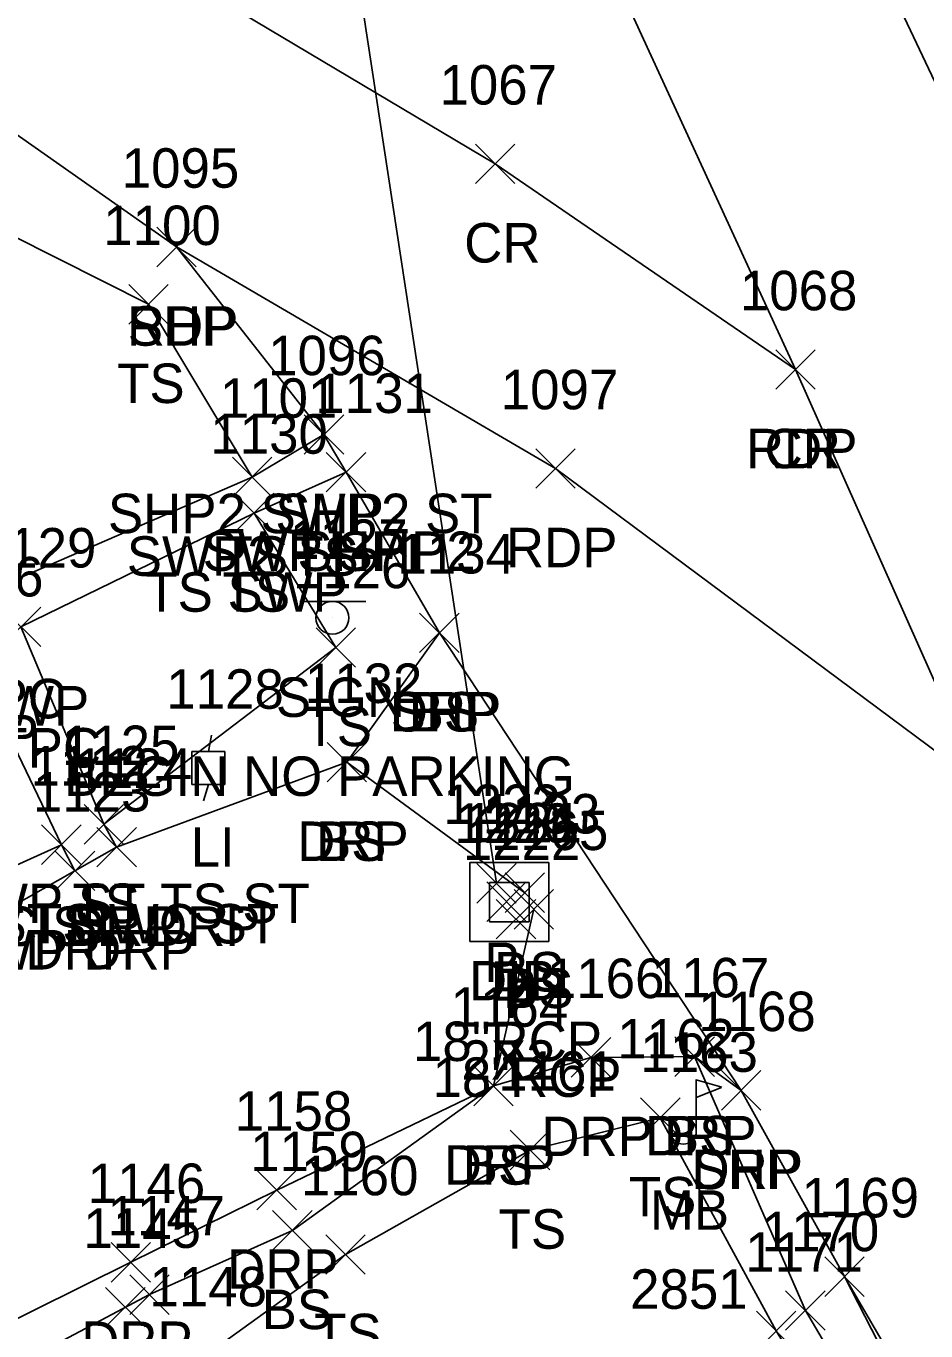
# Model space of a CAD drawing. Extents: x 1504228 to 1506103, y 437717 to 440106.
# Drawn here: x 1505081.8 to 1505127.3, y 438311.9 to 438378 of the extents above; entities that cross this region are included whole.
import ezdxf

# ---------------------------------------------------------------- set-up
doc = ezdxf.new("R2010")
doc.units = 0
for name, color, linetype in [('D_A', 7, 'Continuous'), ('D_C', 7, 'Continuous'), ('D_I', 7, 'Continuous'), ('D_TIC', 7, 'Continuous'), ('DCP', 7, 'Continuous'), ('DD', 7, 'Continuous'), ('DS', 7, 'Continuous'), ('L_A', 7, 'Continuous'), ('L_C', 7, 'Continuous'), ('L_I', 7, 'Continuous'), ('L_TIC', 7, 'Continuous'), ('LBF', 7, 'Continuous'), ('LELB', 7, 'Continuous'), ('LMB', 7, 'Continuous'), ('P_A', 7, 'Continuous'), ('P_I', 7, 'Continuous'), ('P_TIC', 7, 'Continuous'), ('PET', 7, 'Continuous'), ('PRC', 7, 'Continuous'), ('PSP', 7, 'Continuous'), ('R_A', 7, 'Continuous'), ('R_I', 7, 'Continuous'), ('R_TIC', 7, 'Continuous'), ('RDP', 7, 'Continuous'), ('RSW', 7, 'Continuous'), ('S_A', 7, 'Continuous'), ('S_C', 7, 'Continuous'), ('S_I', 7, 'Continuous'), ('SSGN', 7, 'Continuous'), ('U_A', 7, 'Continuous'), ('U_I', 7, 'Continuous'), ('ULP', 7, 'Continuous')]:
    doc.layers.add(name, color=color, linetype=linetype)

msp = doc.modelspace()

# ---------------------------------------------------------------- linework, layer by layer
at = {"layer": 'D_TIC'}
for points in [[(1505104.611, 438333.574), (1505106.611, 438335.574)], [(1505106.611, 438333.574), (1505104.611, 438335.574)], [(1505105.113, 438332.645), (1505107.113, 438334.645)], [(1505107.113, 438332.645), (1505105.113, 438334.645)], [(1505105.599, 438331.757), (1505107.599, 438333.757)], [(1505107.599, 438331.757), (1505105.599, 438333.757)], [(1505122.23, 438313.656), (1505124.23, 438315.656)], [(1505124.23, 438313.656), (1505122.23, 438315.656)], [(1505120.248, 438311.943), (1505122.248, 438313.943)], [(1505122.248, 438311.943), (1505120.248, 438313.943)]]:
    msp.add_lwpolyline(points, dxfattribs=at)
at = {"layer": 'DCP'}
msp.add_lwpolyline([(1505105.611, 438334.574), (1505096.144, 438396.524)], dxfattribs=at)
at = {"layer": 'DD'}
for points in [[(1505123.23, 438314.656), (1505130.775, 438299.935), (1505150.445, 438267.376), (1505153.96, 438259.428), (1505154.819, 438247.207), (1505159.704, 438235.931), (1505164.132, 438229.451)], [(1505121.248, 438312.943), (1505129.281, 438299.278), (1505148.937, 438266.102), (1505152.605, 438259.415), (1505152.899, 438247.284), (1505158.089, 438235.239), (1505161.473, 438228.418)]]:
    msp.add_lwpolyline(points, dxfattribs=at)
at = {"layer": 'DS'}
for p, q in [((1505104.255, 438335.622), (1505108.255, 438335.622)), ((1505104.255, 438331.622), (1505104.255, 438335.622)), ((1505108.255, 438335.622), (1505108.255, 438331.622)), ((1505105.255, 438332.622), (1505105.255, 438334.622)), ((1505105.255, 438334.622), (1505107.255, 438334.622)), ((1505107.255, 438334.622), (1505107.255, 438332.622)), ((1505106.26, 438333.623), (1505106.26, 438333.623)), ((1505106.26, 438333.623), (1505106.26, 438333.623)), ((1505107.255, 438332.622), (1505105.255, 438332.622)), ((1505108.255, 438331.622), (1505104.255, 438331.622))]:
    msp.add_line(p, q, dxfattribs=at)
at = {"layer": 'L_TIC'}
for points in [[(1505086.996, 438362.895), (1505088.996, 438364.895)], [(1505088.996, 438362.895), (1505086.996, 438364.895)], [(1505092.24, 438354.147), (1505094.24, 438356.147)], [(1505094.24, 438354.147), (1505092.24, 438356.147)], [(1505092.336, 438352.326), (1505094.336, 438354.326)], [(1505094.336, 438352.326), (1505092.336, 438354.326)], [(1505101.72, 438346.262), (1505103.72, 438348.262)], [(1505103.72, 438346.262), (1505101.72, 438348.262)], [(1505096.48, 438345.519), (1505098.48, 438347.519)], [(1505098.48, 438345.519), (1505096.48, 438347.519)], [(1505097.031, 438339.705), (1505099.031, 438341.705)], [(1505099.031, 438339.705), (1505097.031, 438341.705)], [(1505084.734, 438336.561), (1505086.734, 438338.561)], [(1505086.734, 438336.561), (1505084.734, 438338.561)], [(1505084.734, 438336.561), (1505086.734, 438338.561)], [(1505086.734, 438336.561), (1505084.734, 438338.561)], [(1505082.583, 438335.527), (1505084.583, 438337.527)], [(1505084.583, 438335.527), (1505082.583, 438337.527)], [(1505085.379, 438335.405), (1505087.379, 438337.405)], [(1505087.379, 438335.405), (1505085.379, 438337.405)], [(1505106.042, 438333.097), (1505108.042, 438335.097)], [(1505108.042, 438333.097), (1505106.042, 438335.097)], [(1505106.496, 438332.257), (1505108.496, 438334.257)], [(1505108.496, 438332.257), (1505106.496, 438334.257)], [(1505114.64, 438324.797), (1505116.64, 438326.797)], [(1505116.64, 438324.797), (1505114.64, 438326.797)], [(1505104.46, 438323.312), (1505106.46, 438325.312)], [(1505106.46, 438323.312), (1505104.46, 438325.312)], [(1505112.899, 438321.703), (1505114.899, 438323.703)], [(1505114.899, 438321.703), (1505112.899, 438323.703)], [(1505106.308, 438320.068), (1505108.308, 438322.068)], [(1505108.308, 438320.068), (1505106.308, 438322.068)], [(1505094.277, 438315.997), (1505096.277, 438317.997)], [(1505096.277, 438315.997), (1505094.277, 438317.997)], [(1505096.967, 438314.777), (1505098.967, 438316.777)], [(1505098.967, 438314.777), (1505096.967, 438316.777)], [(1505087.045, 438312.744), (1505089.045, 438314.744)], [(1505089.045, 438312.744), (1505087.045, 438314.744)], [(1505085.823, 438312.111), (1505087.823, 438314.111)], [(1505087.823, 438312.111), (1505085.823, 438314.111)], [(1505120.248, 438311.943), (1505122.248, 438313.943)], [(1505122.248, 438311.943), (1505120.248, 438313.943)], [(1505118.766, 438310.905), (1505120.766, 438312.905)], [(1505120.766, 438310.905), (1505118.766, 438312.905)]]:
    msp.add_lwpolyline(points, dxfattribs=at)
at = {"layer": 'LBF'}
msp.add_lwpolyline([(1505086.379, 438336.405), (1505085.734, 438337.561)], dxfattribs=at)
at = {"layer": 'LELB'}
for points in [[(1505059.009, 438383.324), (1505071.79, 438372.048), (1505087.996, 438363.895), (1505093.24, 438355.147)], [(1505085.734, 438337.561), (1505097.48, 438346.519), (1505093.336, 438353.326)], [(1505098.031, 438340.705), (1505107.042, 438334.097)], [(1505083.583, 438336.527), (1505067.779, 438329.379), (1505055.432, 438323.4), (1505053.478, 438330.527)], [(1505066.001, 438302.048), (1505088.045, 438313.744), (1505095.277, 438316.997), (1505105.46, 438324.312), (1505107.496, 438333.257)], [(1505115.64, 438325.797), (1505121.248, 438312.943)], [(1505072.779, 438294.246), (1505074.28, 438301.778), (1505090.168, 438310.15), (1505097.967, 438315.777), (1505107.308, 438321.068), (1505113.899, 438322.703), (1505119.766, 438311.905), (1505127.938, 438298.439), (1505147.346, 438265.092)]]:
    msp.add_lwpolyline(points, dxfattribs=at)
at = {"layer": 'LMB'}
for p, q in [((1505115.717, 438324.628), (1505117.011, 438324.246)), ((1505115.723, 438322.036), (1505115.722, 438324.631)), ((1505115.722, 438323.729), (1505117.005, 438324.237)), ((1505115.067, 438322.028), (1505115.067, 438322.028))]:
    msp.add_line(p, q, dxfattribs=at)
msp.add_circle((1505115.067, 438322.027), 0.656, dxfattribs=at)
at = {"layer": 'P_TIC'}
for points in [[(1505104.541, 438370.01), (1505106.541, 438372.01)], [(1505106.541, 438370.01), (1505104.541, 438372.01)], [(1505088.41, 438365.798), (1505090.41, 438367.798)], [(1505090.41, 438365.798), (1505088.41, 438367.798)], [(1505088.41, 438365.798), (1505090.41, 438367.798)], [(1505090.41, 438365.798), (1505088.41, 438367.798)], [(1505119.749, 438359.591), (1505121.749, 438361.591)], [(1505121.749, 438359.591), (1505119.749, 438361.591)], [(1505119.749, 438359.591), (1505121.749, 438361.591)], [(1505121.749, 438359.591), (1505119.749, 438361.591)], [(1505095.876, 438356.305), (1505097.876, 438358.305)], [(1505097.876, 438356.305), (1505095.876, 438358.305)], [(1505096.995, 438354.39), (1505098.995, 438356.39)], [(1505098.995, 438354.39), (1505096.995, 438356.39)], [(1505107.599, 438354.578), (1505109.599, 438356.578)], [(1505109.599, 438354.578), (1505107.599, 438356.578)], [(1505101.72, 438346.262), (1505103.72, 438348.262)], [(1505103.72, 438346.262), (1505101.72, 438348.262)], [(1505116.993, 438323.088), (1505118.993, 438325.088)], [(1505118.993, 438323.088), (1505116.993, 438325.088)], [(1505122.23, 438313.656), (1505124.23, 438315.656)], [(1505124.23, 438313.656), (1505122.23, 438315.656)]]:
    msp.add_lwpolyline(points, dxfattribs=at)
at = {"layer": 'PET'}
for points in [[(1505068.915, 438479.856), (1505088.799, 438434.786), (1505098.18, 438413.38), (1505109.535, 438384.969), (1505120.749, 438360.591), (1505130.106, 438339.585), (1505143.01, 438310.872), (1505160.435, 438272.099), (1505181.323, 438230.832), (1505199.453, 438238.762), (1505211.655, 438244.29), (1505203.781, 438257.456), (1505193.868, 438276.083), (1505183.087, 438301.098), (1505168.267, 438328.998), (1505148.647, 438369.04), (1505141.294, 438386.172), (1505109.448, 438444.779), (1505106.082, 438450.67), (1505101.61, 438460.04), (1505094.486, 438475.336), (1505087.609, 438490.541)], [(1505001.775, 438421.501), (1505032.758, 438402.461), (1505059.812, 438387.625), (1505089.41, 438366.798), (1505108.599, 438355.578), (1505130.106, 438339.585)]]:
    msp.add_lwpolyline(points, dxfattribs=at)
at = {"layer": 'PRC'}
for points in [[(1505079.068, 438483.546), (1505099.188, 438438.177), (1505118.696, 438394.368), (1505142.43, 438344.291), (1505155.616, 438317.19), (1505174.858, 438280.77), (1505189.016, 438255.493), (1505199.453, 438238.762)], [(1505010.682, 438428.714), (1505047.73, 438405.795), (1505081.29, 438385.458), (1505105.541, 438371.01), (1505120.749, 438360.591)]]:
    msp.add_lwpolyline(points, dxfattribs=at)
at = {"layer": 'PSP'}
msp.add_lwpolyline([(1505089.41, 438366.798), (1505096.876, 438357.305), (1505097.995, 438355.39), (1505102.72, 438347.262), (1505117.993, 438324.088), (1505123.23, 438314.656), (1505131.485, 438300.488), (1505151.801, 438269.21), (1505156.465, 438257.693), (1505161.003, 438257.161), (1505164.671, 438254.213), (1505169.777, 438248.987), (1505178.313, 438229.528), (1505181.323, 438230.832)], dxfattribs=at)
at = {"layer": 'R_TIC'}
for points in [[(1505095.876, 438356.305), (1505097.876, 438358.305)], [(1505097.876, 438356.305), (1505095.876, 438358.305)], [(1505092.24, 438354.147), (1505094.24, 438356.147)], [(1505094.24, 438354.147), (1505092.24, 438356.147)], [(1505096.995, 438354.39), (1505098.995, 438356.39)], [(1505098.995, 438354.39), (1505096.995, 438356.39)], [(1505092.336, 438352.326), (1505094.336, 438354.326)], [(1505094.336, 438352.326), (1505092.336, 438354.326)], [(1505080.538, 438346.565), (1505082.538, 438348.565)], [(1505082.538, 438346.565), (1505080.538, 438348.565)], [(1505101.72, 438346.262), (1505103.72, 438348.262)], [(1505103.72, 438346.262), (1505101.72, 438348.262)], [(1505097.031, 438339.705), (1505099.031, 438341.705)], [(1505099.031, 438339.705), (1505097.031, 438341.705)], [(1505084.734, 438336.561), (1505086.734, 438338.561)], [(1505086.734, 438336.561), (1505084.734, 438338.561)], [(1505082.583, 438335.527), (1505084.583, 438337.527)], [(1505084.583, 438335.527), (1505082.583, 438337.527)], [(1505082.583, 438335.527), (1505084.583, 438337.527)], [(1505084.583, 438335.527), (1505082.583, 438337.527)], [(1505085.379, 438335.405), (1505087.379, 438337.405)], [(1505087.379, 438335.405), (1505085.379, 438337.405)], [(1505083.27, 438334.209), (1505085.27, 438336.209)], [(1505085.27, 438334.209), (1505083.27, 438336.209)], [(1505083.27, 438334.209), (1505085.27, 438336.209)], [(1505085.27, 438334.209), (1505083.27, 438336.209)], [(1505109.391, 438324.76), (1505111.391, 438326.76)], [(1505111.391, 438324.76), (1505109.391, 438326.76)], [(1505114.64, 438324.797), (1505116.64, 438326.797)], [(1505116.64, 438324.797), (1505114.64, 438326.797)], [(1505104.46, 438323.312), (1505106.46, 438325.312)], [(1505106.46, 438323.312), (1505104.46, 438325.312)], [(1505116.993, 438323.088), (1505118.993, 438325.088)], [(1505118.993, 438323.088), (1505116.993, 438325.088)], [(1505093.485, 438318.042), (1505095.485, 438320.042)], [(1505095.485, 438318.042), (1505093.485, 438320.042)], [(1505086.097, 438314.384), (1505088.097, 438316.384)], [(1505088.097, 438314.384), (1505086.097, 438316.384)]]:
    msp.add_lwpolyline(points, dxfattribs=at)
at = {"layer": 'RDP'}
for points in [[(1505051.598, 438319.755), (1505054.209, 438320.651), (1505055.718, 438320.206), (1505069.466, 438326.799), (1505084.27, 438335.209), (1505086.379, 438336.405), (1505098.031, 438340.705), (1505102.72, 438347.262)], [(1505067.199, 438305.522), (1505087.097, 438315.384), (1505094.485, 438319.042), (1505105.46, 438324.312), (1505110.391, 438325.76), (1505115.64, 438325.797), (1505117.993, 438324.088)]]:
    msp.add_lwpolyline(points, dxfattribs=at)
at = {"layer": 'RSW'}
for points in [[(1505096.876, 438357.305), (1505093.24, 438355.147), (1505076.603, 438347.927)], [(1505085.734, 438337.561), (1505081.538, 438347.565), (1505093.336, 438353.326), (1505097.995, 438355.39)], [(1505077.756, 438345.437), (1505078.986, 438346.099), (1505083.583, 438336.527), (1505084.27, 438335.209)]]:
    msp.add_lwpolyline(points, dxfattribs=at)
at = {"layer": 'SSGN'}
for p, q in [((1505095.656, 438348.852), (1505098.99, 438348.852)), ((1505097.303, 438348.019), (1505097.303, 438348.019))]:
    msp.add_line(p, q, dxfattribs=at)
msp.add_circle((1505097.303, 438348.019), 0.833, dxfattribs=at)
at = {"layer": 'ULP'}
for p, q in [((1505091.189, 438342.078), (1505091.022, 438341.245)), ((1505090.189, 438339.578), (1505090.189, 438341.245)), ((1505090.189, 438341.245), (1505091.855, 438341.245)), ((1505091.855, 438341.245), (1505091.855, 438339.578)), ((1505091.022, 438340.412), (1505091.022, 438340.412)), ((1505091.855, 438339.578), (1505090.189, 438339.578)), ((1505090.772, 438338.745), (1505091.022, 438339.578))]:
    msp.add_line(p, q, dxfattribs=at)

# ---------------------------------------------------------------- texts
at = {"layer": 'D_A'}
for s, p in [('P', (1505104.989, 438329.574)), ('DIB', (1505104.215, 438328.645)), ('DI', (1505105.315, 438328.623)), ('P', (1505105.977, 438327.757))]:
    msp.add_text(s, height=2, dxfattribs=at).set_placement(p)
at = {"layer": 'D_C'}
for s, p in [('18"RCP', (1505101.383, 438325.574)), ('2X2', (1505103.835, 438324.623)), ('18"RCP', (1505102.371, 438323.757))]:
    msp.add_text(s, height=2, dxfattribs=at).set_placement(p)
at = {"layer": 'D_I'}
for s, p in [('1223', (1505102.918, 438337.574)), ('1220', (1505103.481, 438336.623)), ('1221', (1505103.987, 438336.645)), ('1222', (1505103.906, 438335.757)), ('1169', (1505121.049, 438317.656)), ('1170', (1505119.035, 438315.943))]:
    msp.add_text(s, height=2, dxfattribs=at).set_placement(p)
at = {"layer": 'L_A'}
for s, p in [('TS', (1505086.405, 438358.895)), ('TS', (1505091.649, 438350.147)), ('TS', (1505091.745, 438348.326)), ('SWP2 STPC', (1505068.359, 438342.927)), ('BS', (1505101.161, 438342.262)), ('TS', (1505095.89, 438341.519)), ('SWP ST STPC', (1505067.465, 438340.437)), ('BS', (1505096.472, 438335.705)), ('STPC SWP ST TS ST', (1505069.71, 438332.561)), ('TS', (1505084.143, 438332.561)), ('STPC ST  DRP', (1505075.237, 438331.405)), ('TS', (1505081.993, 438331.527)), ('BS', (1505105.483, 438329.097)), ('BS', (1505105.937, 438328.257)), ('BS', (1505114.081, 438320.797)), ('BS', (1505103.9, 438319.312)), ('TS', (1505112.309, 438317.703)), ('MB', (1505113.374, 438317.027)), ('TS', (1505105.717, 438316.068)), ('BS', (1505093.718, 438311.997)), ('TS', (1505096.377, 438310.777))]:
    msp.add_text(s, height=2, dxfattribs=at).set_placement(p)
at = {"layer": 'L_C'}
msp.add_text('2851', height=2, dxfattribs=at).set_placement((1505112.374, 438313.027))
at = {"layer": 'L_I'}
for s, p in [('1100', (1505085.704, 438366.895)), ('1101', (1505091.602, 438358.147)), ('1130', (1505091.123, 438356.326)), ('1134', (1505100.594, 438350.262)), ('1126', (1505095.299, 438349.519)), ('1132', (1505095.905, 438343.705)), ('1125', (1505083.608, 438340.561)), ('1125', (1505083.608, 438340.561)), ('1112', (1505082.024, 438339.527)), ('1124', (1505084.253, 438339.405)), ('1133', (1505104.916, 438337.097)), ('1165', (1505105.322, 438336.257)), ('1167', (1505113.467, 438328.797)), ('1164', (1505103.286, 438327.312)), ('1162', (1505111.726, 438325.703)), ('1163', (1505112.894, 438325.027)), ('1161', (1505105.702, 438324.068)), ('1159', (1505093.144, 438319.997)), ('1160', (1505095.707, 438318.777)), ('1147', (1505085.919, 438316.744)), ('1145', (1505084.697, 438316.111)), ('1170', (1505119.035, 438315.943)), ('1171', (1505118.207, 438314.905)), ('1148', (1505088.042, 438313.15)), ('1148', (1505088.042, 438313.15))]:
    msp.add_text(s, height=2, dxfattribs=at).set_placement(p)
at = {"layer": 'P_A'}
for s, p in [('CR', (1505103.974, 438366.01)), ('SHP', (1505086.946, 438361.798)), ('RDP', (1505086.898, 438361.798)), ('RDP', (1505118.238, 438355.591)), ('CR', (1505119.182, 438355.591)), ('SHP', (1505094.412, 438352.305)), ('SHP', (1505095.531, 438350.39)), ('RDP', (1505106.087, 438350.578)), ('SHP', (1505100.255, 438342.262)), ('SHP', (1505115.528, 438319.088))]:
    msp.add_text(s, height=2, dxfattribs=at).set_placement(p)
at = {"layer": 'P_I'}
for s, p in [('1067', (1505102.723, 438374.01)), ('1095', (1505086.638, 438369.798)), ('1095', (1505086.638, 438369.798)), ('1068', (1505117.93, 438363.591)), ('1068', (1505117.93, 438363.591)), ('1096', (1505094.049, 438360.305)), ('1131', (1505096.436, 438358.39)), ('1097', (1505105.827, 438358.578)), ('1134', (1505100.594, 438350.262)), ('1168', (1505115.82, 438327.088)), ('1169', (1505121.049, 438317.656))]:
    msp.add_text(s, height=2, dxfattribs=at).set_placement(p)
at = {"layer": 'R_A'}
for s, p in [('SHP2 SWP2 ST', (1505085.939, 438352.305)), ('SWP2 TS', (1505086.893, 438350.147)), ('SWP SHP2', (1505090.735, 438350.39)), ('TS SWP', (1505087.832, 438348.326)), ('SWP2 STPC', (1505068.359, 438342.927)), ('SWP', (1505078.901, 438342.565)), ('DRP', (1505100.208, 438342.262)), ('SWP', (1505076.348, 438341.099)), ('SWP ST STPC', (1505067.465, 438340.437)), ('DRP', (1505095.519, 438335.705)), ('STPC SWP ST TS ST', (1505069.71, 438332.561)), ('SWP TS2 ST SWC ST', (1505067.56, 438331.527)), ('SWP TS2 ST SWC ST', (1505067.56, 438331.527)), ('DRP', (1505083.867, 438331.405)), ('SWP DRP', (1505077.853, 438330.209)), ('DRP', (1505081.759, 438330.209)), ('DRP', (1505107.879, 438320.76)), ('DRP', (1505113.129, 438320.797)), ('DRP', (1505102.948, 438319.312)), ('DRP', (1505115.481, 438319.088)), ('DRP', (1505091.973, 438314.042)), ('DRP', (1505084.585, 438310.384))]:
    msp.add_text(s, height=2, dxfattribs=at).set_placement(p)
at = {"layer": 'R_I'}
for s, p in [('1096', (1505094.049, 438360.305)), ('1101', (1505091.602, 438358.147)), ('1131', (1505096.436, 438358.39)), ('1130', (1505091.123, 438356.326)), ('1129', (1505079.405, 438350.565)), ('1134', (1505100.594, 438350.262)), ('1106', (1505076.726, 438349.099)), ('1132', (1505095.905, 438343.705)), ('1125', (1505083.608, 438340.561)), ('1112', (1505082.024, 438339.527)), ('1112', (1505082.024, 438339.527)), ('1124', (1505084.253, 438339.405)), ('1123', (1505082.145, 438338.209)), ('1123', (1505082.145, 438338.209)), ('1166', (1505108.163, 438328.76)), ('1167', (1505113.467, 438328.797)), ('1164', (1505103.286, 438327.312)), ('1168', (1505115.82, 438327.088)), ('1158', (1505092.359, 438322.042)), ('1146', (1505084.916, 438318.384))]:
    msp.add_text(s, height=2, dxfattribs=at).set_placement(p)
at = {"layer": 'S_A'}
msp.add_text('SIGN', height=2, dxfattribs=at).set_placement((1505094.441, 438342.999))
at = {"layer": 'S_C'}
msp.add_text('BEGIN NO PARKING', height=2, dxfattribs=at).set_placement((1505083.717, 438338.999))
at = {"layer": 'S_I'}
msp.add_text('1127', height=2, dxfattribs=at).set_placement((1505095.158, 438350.999))
at = {"layer": 'U_A'}
msp.add_text('LI', height=2, dxfattribs=at).set_placement((1505090.124, 438335.412))
at = {"layer": 'U_I'}
msp.add_text('1128', height=2, dxfattribs=at).set_placement((1505088.896, 438343.412))

doc.saveas('drawing.dxf')
